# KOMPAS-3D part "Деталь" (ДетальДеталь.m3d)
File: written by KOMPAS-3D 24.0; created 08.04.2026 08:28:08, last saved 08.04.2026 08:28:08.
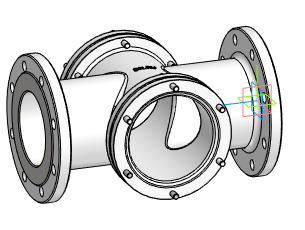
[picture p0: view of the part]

Document properties: Автор: Main; Полное имя файла: D:\DN.ru Аутсерс\Стекло смотровое DN.ru\Исходники\Стекло смотровое DN.ru SG2-34G-F тип В ГОСТ 21836-2021 Ду125 Ру16, углеродистая сталь, фланцевое\ДетальДеталь.m3d

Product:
- Body: Твердое тело1  | qty 1
- Part/product: Деталь
    additional columns: Типовые

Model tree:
1. Твердое тело1  (labels: Твердое тело1)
